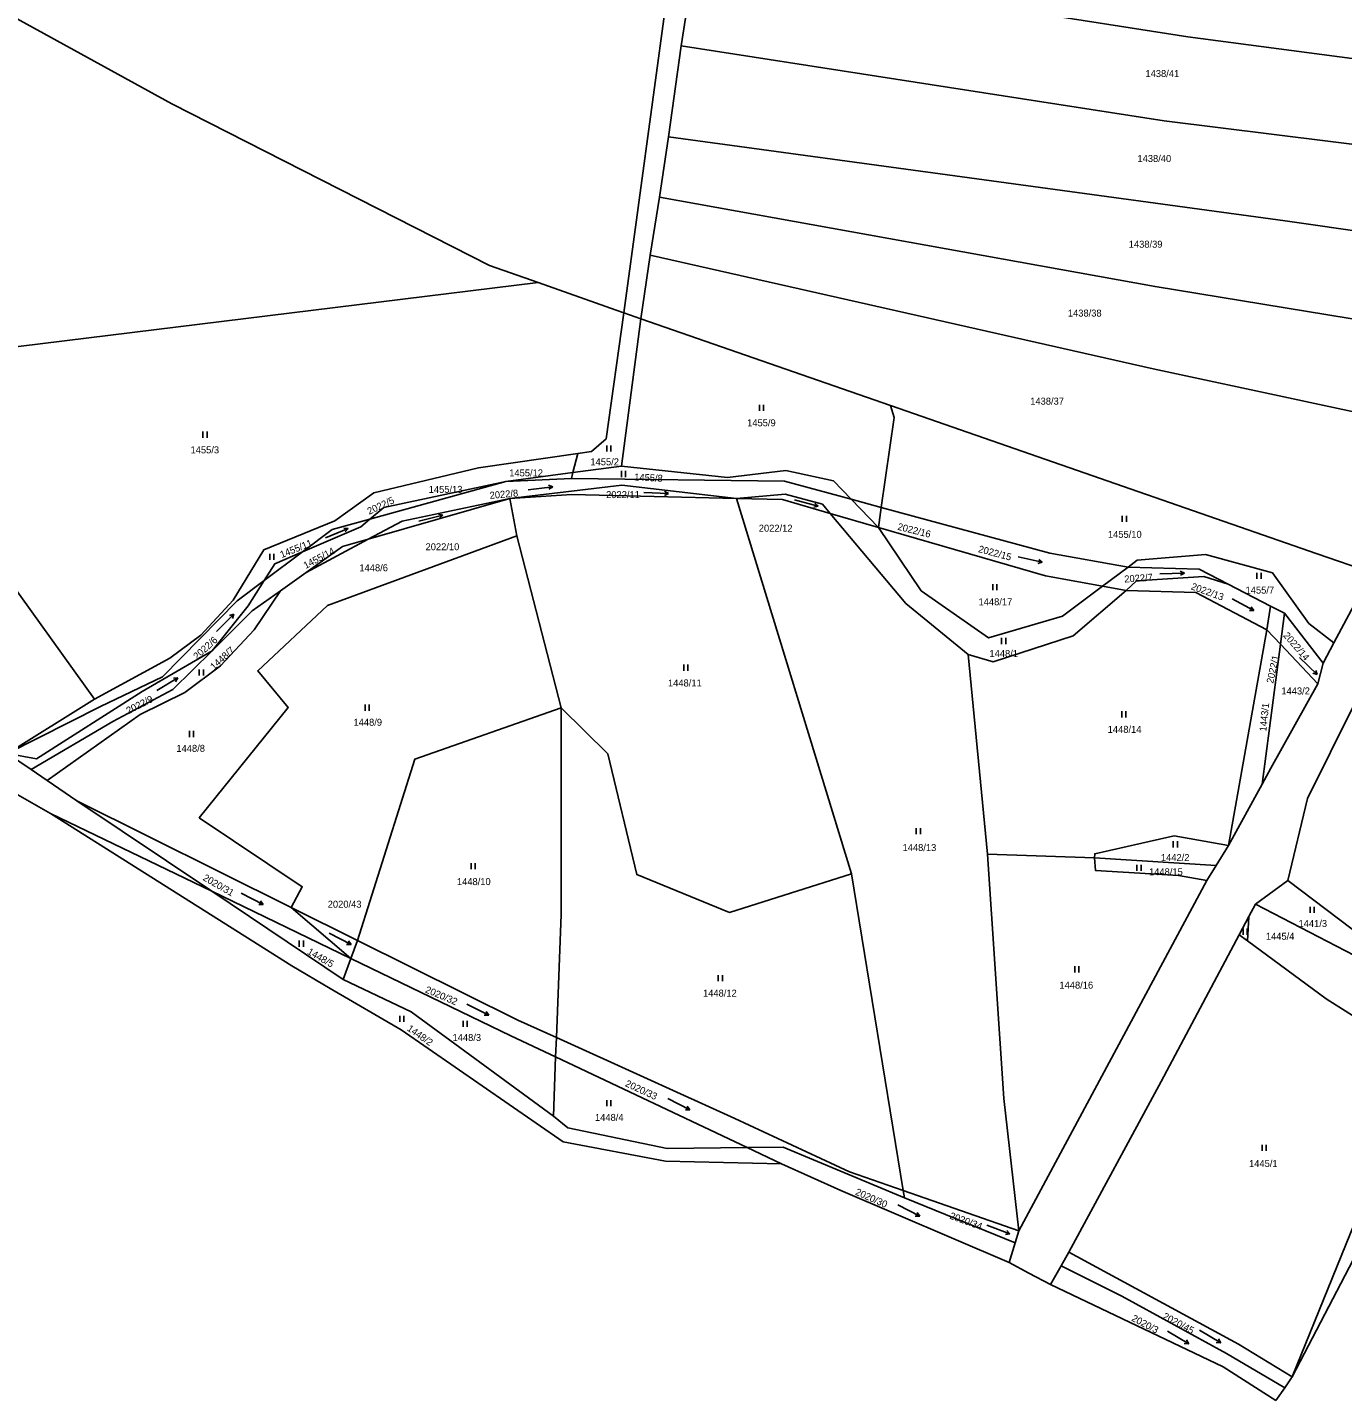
# Model space of a CAD drawing. Extents: x -793666 to -785424, y -1118958 to -1108761.
# Drawn here: x -787563.2 to -787242.9, y -1118639.5 to -1118305 of the extents above; entities that cross this region are included whole.
import ezdxf

# ---------------------------------------------------------------- set-up
doc = ezdxf.new("R2010")
doc.units = 0
for name, color, linetype in [('Hranice parcel', 7, 'Continuous'), ('Parcelní čísla', 7, 'Continuous'), ('Značky kultur', 7, 'Continuous')]:
    doc.layers.add(name, color=color, linetype=linetype)

msp = doc.modelspace()

# ---------------------------------------------------------------- linework, layer by layer
at = {"layer": 'Hranice parcel'}
for p, q in [((-787417.9, -1118374.55), (-787402.57, -1118261.44)), ((-787404, -1118309.48), (-787400.74, -1118288.44)), ((-787407.09, -1118331.67), (-787404, -1118309.48)), ((-787409.24, -1118346.36), (-787407.09, -1118331.67)), ((-787411.56, -1118360.49), (-787409.24, -1118346.36)), ((-787413.8, -1118375.97), (-787411.56, -1118360.49)), ((-787629.87, -1118390.63), (-787438.82, -1118367.18)), ((-787418.52, -1118411.86), (-787413.8, -1118375.97)), ((-787413.8, -1118375.97), (-787417.9, -1118374.55)), ((-787413.8, -1118375.97), (-787353.01, -1118397.09)), ((-787429.1, -1118408.81), (-787430.33, -1118413.45)), ((-787446.64, -1118415.65), (-787430.33, -1118413.45)), ((-787430.33, -1118413.45), (-787430.71, -1118414.9)), ((-787430.33, -1118413.45), (-787418.52, -1118411.86)), ((-787479.78, -1118424.76), (-787446.64, -1118415.65)), ((-787446.64, -1118415.65), (-787430.71, -1118414.9)), ((-787445.72, -1118419.74), (-787480.16, -1118429.65)), ((-787443.96, -1118428.82), (-787445.72, -1118419.74)), ((-787362.53, -1118511.14), (-787390.51, -1118419.78)), ((-787362.57, -1118419.94), (-787355.26, -1118421.92)), ((-787355.96, -1118426.79), (-787362.57, -1118419.94)), ((-787355.96, -1118426.79), (-787367.67, -1118423.39)), ((-787355.26, -1118421.92), (-787355.96, -1118426.79)), ((-787495.27, -1118437.74), (-787480.16, -1118429.65)), ((-787433.19, -1118470.77), (-787443.96, -1118428.82)), ((-787505.48, -1118439.7), (-787496.22, -1118432.75)), ((-787495.27, -1118437.74), (-787501.57, -1118442.22)), ((-787295.11, -1118436.5), (-787301.35, -1118441.14)), ((-787235.84, -1118437.8), (-787245.01, -1118454.92)), ((-787295.65, -1118442.18), (-787301.35, -1118441.14)), ((-787270.8, -1118440.61), (-787260.47, -1118445.96)), ((-787260.47, -1118445.96), (-787261.35, -1118451.77)), ((-787257.07, -1118447.72), (-787260.47, -1118445.96)), ((-787258.06, -1118455.25), (-787257.07, -1118447.72)), ((-787257.07, -1118447.72), (-787247.66, -1118459.87)), ((-787261.35, -1118451.77), (-787270.69, -1118504.24)), ((-787258.06, -1118455.25), (-787261.35, -1118451.77)), ((-787329.35, -1118506.42), (-787334.09, -1118457.75)), ((-787262.52, -1118489.37), (-787258.06, -1118455.25)), ((-787248.91, -1118464.91), (-787258.06, -1118455.25)), ((-787245.01, -1118454.92), (-787247.66, -1118459.87)), ((-787247.66, -1118459.87), (-787248.91, -1118464.91)), ((-787546.81, -1118468.61), (-787568, -1118481.84)), ((-787562.27, -1118485.78), (-787568, -1118481.84)), ((-787557.53, -1118496.48), (-787576.6, -1118485.68)), ((-787558.39, -1118488.44), (-787562.27, -1118485.78)), ((-787551.16, -1118493.41), (-787558.39, -1118488.44)), ((-787270.69, -1118504.24), (-787262.52, -1118489.37)), ((-787518.29, -1118515.43), (-787551.16, -1118493.41)), ((-787498.93, -1118519.35), (-787551.16, -1118493.41)), ((-787498.76, -1118533.58), (-787557.53, -1118496.48)), ((-787518.29, -1118515.43), (-787557.53, -1118496.48)), ((-787270.69, -1118504.24), (-787273.7, -1118509.14)), ((-787329.35, -1118506.42), (-787303.31, -1118507.31)), ((-787303.31, -1118507.31), (-787273.7, -1118509.14)), ((-787349.9, -1118588.32), (-787362.53, -1118511.14)), ((-787273.7, -1118509.14), (-787275.95, -1118512.79)), ((-787275.95, -1118512.79), (-787321.76, -1118598.1)), ((-787264.16, -1118518.6), (-787256.27, -1118512.79)), ((-787518.29, -1118515.43), (-787484.4, -1118531.8)), ((-787486.26, -1118536.89), (-787518.29, -1118515.43)), ((-787484.4, -1118531.8), (-787498.93, -1118519.35)), ((-787482.79, -1118527.37), (-787498.93, -1118519.35)), ((-787265.75, -1118521.6), (-787264.16, -1118518.6)), ((-787268.09, -1118526), (-787265.75, -1118521.6)), ((-787265.75, -1118521.6), (-787266.06, -1118527.5)), ((-787482.79, -1118527.37), (-787484.4, -1118531.8)), ((-787266.06, -1118527.5), (-787268.09, -1118526)), ((-787489.41, -1118539.07), (-787498.76, -1118533.58)), ((-787484.4, -1118531.8), (-787486.26, -1118536.89)), ((-787472.16, -1118549.19), (-787489.41, -1118539.07)), ((-787434.54, -1118555.77), (-787434.36, -1118551.03)), ((-787435.08, -1118570.18), (-787434.54, -1118555.77)), ((-787434.54, -1118555.77), (-787387.94, -1118577.81)), ((-787217.11, -1118560.49), (-787255.19, -1118633.7)), ((-787379.56, -1118581.78), (-787387.94, -1118577.81)), ((-787365.06, -1118588.3), (-787379.56, -1118581.78)), ((-787324.12, -1118605.87), (-787365.06, -1118588.3)), ((-787349.61, -1118590.09), (-787349.9, -1118588.32)), ((-787321.76, -1118598.1), (-787349.9, -1118588.32)), ((-787322.66, -1118601.06), (-787349.61, -1118590.09)), ((-787321.76, -1118598.1), (-787322.66, -1118601.06)), ((-787322.66, -1118601.06), (-787324.12, -1118605.87)), ((-787311.47, -1118606.64), (-787309.57, -1118603.31)), ((-787311.47, -1118606.64), (-787314.06, -1118611.19)), ((-787272.02, -1118631.21), (-787314.06, -1118611.19)), ((-787259.14, -1118639.46), (-787272.02, -1118631.21)), ((-787255.19, -1118633.7), (-787257, -1118636.34)), ((-787259.14, -1118639.46), (-787257, -1118636.34))]:
    msp.add_line(p, q, dxfattribs=at)
for points in [[(-787438.82, -1118367.18), (-787450.68, -1118362.99), (-787528.04, -1118323.66), (-787620.89, -1118272.58)], [(-787170.53, -1118319.75), (-787225.85, -1118314.51), (-787280.62, -1118307.34), (-787400.74, -1118288.44)], [(-787181.11, -1118339.31), (-787219.07, -1118336.16), (-787286.38, -1118327.77), (-787404, -1118309.48)], [(-787192.93, -1118361.27), (-787256.87, -1118352.13), (-787407.09, -1118331.67)], [(-787204.45, -1118381.96), (-787288.56, -1118368.12), (-787409.24, -1118346.36)], [(-787216.75, -1118403.66), (-787289.04, -1118388.21), (-787411.56, -1118360.49)], [(-787417.9, -1118374.55), (-787419.84, -1118373.88), (-787438.82, -1118367.18)], [(-787417.9, -1118374.55), (-787422.24, -1118405.26), (-787425.81, -1118408.34), (-787429.1, -1118408.81)], [(-787617.06, -1118409.72), (-787598.89, -1118396.21), (-787546.81, -1118468.61)], [(-787355.26, -1118421.92), (-787352.13, -1118400.04), (-787353.01, -1118397.09)], [(-787353.01, -1118397.09), (-787249.07, -1118433.2), (-787235.84, -1118437.8)], [(-787546.81, -1118468.61), (-787528.49, -1118458.66), (-787520.97, -1118453.07), (-787513.06, -1118444.49), (-787505.63, -1118432.22), (-787488.3, -1118425.19), (-787478.83, -1118418.38), (-787453.3, -1118412.3), (-787429.1, -1118408.81)], [(-787362.57, -1118419.94), (-787366.89, -1118415.46), (-787378.48, -1118412.97), (-787392.73, -1118414.6), (-787418.52, -1118411.86)], [(-787479.78, -1118424.76), (-787476.41, -1118421.91), (-787446.64, -1118415.65)], [(-787445.72, -1118419.74), (-787418.4, -1118416.52), (-787390.51, -1118419.78)], [(-787430.71, -1118414.9), (-787378.79, -1118415.54), (-787362.57, -1118419.94)], [(-787480.16, -1118429.65), (-787471.92, -1118425.24), (-787445.72, -1118419.74)], [(-787390.51, -1118419.78), (-787430.63, -1118418.78), (-787445.72, -1118419.74)], [(-787390.51, -1118419.78), (-787378.63, -1118418.69), (-787369.58, -1118421.11), (-787367.67, -1118423.39)], [(-787367.67, -1118423.39), (-787379.27, -1118420.02), (-787390.51, -1118419.78)], [(-787367.67, -1118423.39), (-787349.3, -1118445.29), (-787334.09, -1118457.75)], [(-787355.26, -1118421.92), (-787314.2, -1118433.05), (-787295.11, -1118436.5)], [(-787496.22, -1118432.75), (-787482, -1118426.63), (-787479.78, -1118424.76)], [(-787496.22, -1118432.75), (-787488.92, -1118427.27), (-787479.78, -1118424.76)], [(-787301.35, -1118441.14), (-787315.26, -1118438.6), (-787355.96, -1118426.79)], [(-787301.35, -1118441.14), (-787311.09, -1118448.38), (-787329.12, -1118453.71), (-787345.51, -1118442.25), (-787355.96, -1118426.79)], [(-787498.93, -1118519.35), (-787496.26, -1118514.3), (-787521.34, -1118497.53), (-787499.69, -1118470.65), (-787507.08, -1118461.72), (-787490.08, -1118445.83), (-787443.96, -1118428.82)], [(-787480.16, -1118429.65), (-787486.45, -1118431.46), (-787495.27, -1118437.74)], [(-787505.48, -1118439.7), (-787502.91, -1118435.63), (-787496.22, -1118432.75)], [(-787245.01, -1118454.92), (-787251.12, -1118450.22), (-787260.01, -1118437.85), (-787276.27, -1118433.38), (-787292.97, -1118434.78), (-787295.11, -1118436.5)], [(-787295.11, -1118436.5), (-787277.84, -1118436.97), (-787270.8, -1118440.61)], [(-787568, -1118481.84), (-787545.35, -1118470.42), (-787530.31, -1118463.17), (-787512.07, -1118444.65), (-787505.48, -1118439.7)], [(-787518.2, -1118456.82), (-787509.39, -1118445.9), (-787505.48, -1118439.7)], [(-787295.65, -1118442.18), (-787293.11, -1118439.81), (-787276.71, -1118438.78), (-787270.8, -1118440.61)], [(-787558.39, -1118488.44), (-787535.74, -1118472.39), (-787524.84, -1118466.98), (-787516.12, -1118460.49), (-787507.98, -1118451.76), (-787501.57, -1118442.22)], [(-787501.57, -1118442.22), (-787508.48, -1118447.13), (-787518.2, -1118456.82)], [(-787334.09, -1118457.75), (-787328.03, -1118459.56), (-787308.54, -1118453.2), (-787295.65, -1118442.18)], [(-787261.35, -1118451.77), (-787278.62, -1118442.65), (-787295.65, -1118442.18)], [(-787568, -1118481.84), (-787560.99, -1118483.15), (-787535.23, -1118466.77), (-787518.2, -1118456.82)], [(-787518.2, -1118456.82), (-787527.72, -1118466.31), (-787542.34, -1118474.1), (-787562.27, -1118485.78)], [(-787248.91, -1118464.91), (-787260.38, -1118485.47), (-787262.52, -1118489.37)], [(-787482.79, -1118527.37), (-787468.81, -1118483.23), (-787433.19, -1118470.77)], [(-787434.36, -1118551.03), (-787433.23, -1118521.06), (-787433.19, -1118470.77)], [(-787433.19, -1118470.77), (-787421.86, -1118481.96), (-787414.81, -1118511.34), (-787392.19, -1118520.57), (-787362.53, -1118511.14)], [(-787256.27, -1118512.79), (-787251.49, -1118492.81), (-787240.28, -1118470.25)], [(-787270.69, -1118504.24), (-787283.94, -1118501.92), (-787303.28, -1118506.29), (-787303.31, -1118507.31)], [(-787321.76, -1118598.1), (-787325.42, -1118565.9), (-787329.35, -1118506.42)], [(-787303.31, -1118507.31), (-787303.09, -1118510.36), (-787282.85, -1118511.55), (-787275.95, -1118512.79)], [(-787264.16, -1118518.6), (-787240, -1118531.03), (-787237.55, -1118526.92), (-787256.27, -1118512.79)], [(-787434.36, -1118551.03), (-787443.72, -1118546.78), (-787482.79, -1118527.37)], [(-787268.09, -1118526), (-787287.1, -1118561.77), (-787309.57, -1118603.31)], [(-787217.11, -1118560.49), (-787246.95, -1118541.62), (-787266.06, -1118527.5)], [(-787484.4, -1118531.8), (-787445.44, -1118550.61), (-787434.54, -1118555.77)], [(-787435.08, -1118570.18), (-787469.71, -1118544.75), (-787486.26, -1118536.89)], [(-787379.56, -1118581.78), (-787407.83, -1118581.15), (-787432.67, -1118576.48), (-787472.16, -1118549.19)], [(-787349.9, -1118588.32), (-787363.02, -1118583.76), (-787390.92, -1118570.77), (-787434.36, -1118551.03)], [(-787255.19, -1118633.7), (-787235.57, -1118585.27), (-787217.11, -1118560.49)], [(-787387.94, -1118577.81), (-787407.41, -1118578.04), (-787431.54, -1118573.02), (-787435.08, -1118570.18)], [(-787349.61, -1118590.09), (-787379.13, -1118577.71), (-787387.94, -1118577.81)], [(-787309.57, -1118603.31), (-787268.28, -1118625.73), (-787255.19, -1118633.7)], [(-787314.06, -1118611.19), (-787319.31, -1118608.45), (-787324.12, -1118605.87)], [(-787257, -1118636.34), (-787271.2, -1118628.01), (-787296.71, -1118614.01), (-787311.47, -1118606.64)]]:
    msp.add_lwpolyline(points, dxfattribs=at)
at = {"layer": 'Značky kultur'}
for p, q in [((-787384.91, -1118398.41), (-787384.91, -1118396.91)), ((-787383.91, -1118398.41), (-787383.91, -1118396.91)), ((-787520.42, -1118404.95), (-787520.42, -1118403.45)), ((-787519.42, -1118404.95), (-787519.42, -1118403.45)), ((-787422.09, -1118408.31), (-787422.09, -1118406.81)), ((-787421.09, -1118408.31), (-787421.09, -1118406.81)), ((-787418.54, -1118414.52), (-787418.54, -1118413.02)), ((-787417.54, -1118414.52), (-787417.54, -1118413.02)), ((-787441.22, -1118417.62), (-787435.26, -1118416.89)), ((-787435.26, -1118416.89), (-787436.3, -1118416.51)), ((-787435.26, -1118416.89), (-787436.17, -1118417.51)), ((-787413.07, -1118418.32), (-787407.08, -1118418.53)), ((-787407.08, -1118418.53), (-787408.07, -1118419)), ((-787407.08, -1118418.53), (-787408.03, -1118418)), ((-787376.38, -1118420.1), (-787370.59, -1118421.65)), ((-787370.59, -1118421.65), (-787371.4, -1118420.91)), ((-787467.83, -1118425.26), (-787462.01, -1118423.81)), ((-787462.01, -1118423.81), (-787463.08, -1118423.56)), ((-787462.01, -1118423.81), (-787462.84, -1118424.53)), ((-787370.59, -1118421.65), (-787371.66, -1118421.88)), ((-787296.55, -1118425.45), (-787296.55, -1118423.95)), ((-787295.55, -1118425.45), (-787295.55, -1118423.95)), ((-787490.62, -1118429.31), (-787485.06, -1118427.07)), ((-787485.06, -1118427.07), (-787486.15, -1118426.97)), ((-787485.06, -1118427.07), (-787485.78, -1118427.9)), ((-787504.13, -1118434.72), (-787504.13, -1118433.22)), ((-787503.13, -1118434.72), (-787503.13, -1118433.22)), ((-787321.9, -1118433.94), (-787316.05, -1118435.29)), ((-787316.05, -1118435.29), (-787316.89, -1118434.58)), ((-787316.05, -1118435.29), (-787317.12, -1118435.56)), ((-787287.43, -1118438.12), (-787281.43, -1118437.91)), ((-787281.43, -1118437.91), (-787282.43, -1118437.45)), ((-787281.43, -1118437.91), (-787282.39, -1118438.45)), ((-787263.78, -1118439.33), (-787263.78, -1118437.83)), ((-787262.78, -1118439.33), (-787262.78, -1118437.83)), ((-787328.1, -1118442.12), (-787328.1, -1118440.62)), ((-787327.1, -1118442.12), (-787327.1, -1118440.62)), ((-787269.81, -1118444.22), (-787264.51, -1118447.03)), ((-787517.14, -1118452.16), (-787512.9, -1118447.91)), ((-787512.9, -1118447.91), (-787513.95, -1118448.25)), ((-787512.9, -1118447.91), (-787513.24, -1118448.96)), ((-787264.51, -1118447.03), (-787265.61, -1118447.02)), ((-787264.51, -1118447.03), (-787265.14, -1118446.13)), ((-787325.95, -1118455.22), (-787325.95, -1118453.72)), ((-787324.95, -1118455.22), (-787324.95, -1118453.72)), ((-787521.32, -1118462.9), (-787521.32, -1118461.4)), ((-787520.32, -1118462.9), (-787520.32, -1118461.4)), ((-787403.34, -1118461.71), (-787403.34, -1118460.21)), ((-787402.34, -1118461.71), (-787402.34, -1118460.21)), ((-787253.39, -1118458.48), (-787249.08, -1118462.65)), ((-787531.64, -1118466.53), (-787526.5, -1118463.44)), ((-787526.5, -1118463.44), (-787527.59, -1118463.52)), ((-787526.5, -1118463.44), (-787527.08, -1118464.38)), ((-787249.08, -1118462.65), (-787250.13, -1118462.33)), ((-787249.08, -1118462.65), (-787249.43, -1118461.61)), ((-787480.94, -1118471.46), (-787480.94, -1118469.96)), ((-787479.94, -1118471.46), (-787479.94, -1118469.96)), ((-787296.7, -1118473.09), (-787296.7, -1118471.59)), ((-787295.7, -1118473.09), (-787295.7, -1118471.59)), ((-787523.7, -1118477.86), (-787523.7, -1118476.36)), ((-787522.7, -1118477.86), (-787522.7, -1118476.36)), ((-787346.73, -1118501.53), (-787346.73, -1118500.03)), ((-787345.73, -1118501.53), (-787345.73, -1118500.03)), ((-787284.15, -1118504.75), (-787284.15, -1118503.25)), ((-787283.15, -1118504.75), (-787283.15, -1118503.25)), ((-787455.14, -1118510.06), (-787455.14, -1118508.56)), ((-787454.14, -1118510.06), (-787454.14, -1118508.56)), ((-787292.98, -1118510.47), (-787292.98, -1118508.97)), ((-787291.98, -1118510.47), (-787291.98, -1118508.97)), ((-787511.1, -1118515.92), (-787505.76, -1118518.65)), ((-787505.76, -1118518.65), (-787506.4, -1118517.76)), ((-787505.76, -1118518.65), (-787506.85, -1118518.65)), ((-787250.82, -1118520.69), (-787250.82, -1118519.19)), ((-787249.82, -1118520.69), (-787249.82, -1118519.19)), ((-787267.14, -1118526.02), (-787267.14, -1118524.52)), ((-787266.14, -1118526.02), (-787266.14, -1118524.52)), ((-787496.98, -1118528.92), (-787496.98, -1118527.42)), ((-787495.98, -1118528.92), (-787495.98, -1118527.42)), ((-787489.68, -1118525.65), (-787484.34, -1118528.38)), ((-787484.34, -1118528.38), (-787484.98, -1118527.49)), ((-787484.34, -1118528.38), (-787485.43, -1118528.38)), ((-787308.11, -1118535.2), (-787308.11, -1118533.7)), ((-787307.11, -1118535.2), (-787307.11, -1118533.7)), ((-787394.93, -1118537.32), (-787394.93, -1118535.82)), ((-787393.93, -1118537.32), (-787393.93, -1118535.82)), ((-787456.19, -1118542.88), (-787450.85, -1118545.61)), ((-787450.85, -1118545.61), (-787451.49, -1118544.72)), ((-787472.5, -1118547.26), (-787472.5, -1118545.76)), ((-787471.5, -1118547.26), (-787471.5, -1118545.76)), ((-787457.09, -1118548.46), (-787457.09, -1118546.96)), ((-787456.09, -1118548.46), (-787456.09, -1118546.96)), ((-787450.85, -1118545.61), (-787451.94, -1118545.61)), ((-787422.07, -1118567.78), (-787422.07, -1118566.28)), ((-787421.07, -1118567.78), (-787421.07, -1118566.28)), ((-787407.2, -1118565.9), (-787401.86, -1118568.63)), ((-787401.86, -1118568.63), (-787402.5, -1118567.74)), ((-787401.86, -1118568.63), (-787402.95, -1118568.63)), ((-787262.5, -1118578.64), (-787262.5, -1118577.14)), ((-787261.5, -1118578.64), (-787261.5, -1118577.14)), ((-787351.22, -1118591.82), (-787345.88, -1118594.55)), ((-787345.88, -1118594.55), (-787346.97, -1118594.55)), ((-787345.88, -1118594.55), (-787346.52, -1118593.66)), ((-787329.54, -1118596.74), (-787323.94, -1118598.89)), ((-787323.94, -1118598.89), (-787324.67, -1118598.07)), ((-787323.94, -1118598.89), (-787325.03, -1118599.01)), ((-787285.52, -1118622.53), (-787280.38, -1118625.62)), ((-787280.38, -1118625.62), (-787280.96, -1118624.69)), ((-787277.73, -1118622.31), (-787272.59, -1118625.4)), ((-787272.59, -1118625.4), (-787273.17, -1118624.47)), ((-787280.38, -1118625.62), (-787281.47, -1118625.55)), ((-787272.59, -1118625.4), (-787273.68, -1118625.33))]:
    msp.add_line(p, q, dxfattribs=at)

# ---------------------------------------------------------------- texts
at = {"layer": 'Parcelní čísla'}
for s, p in [('1438/41', (-787290.92, -1118317.11)), ('1438/40', (-787292.87, -1118337.79)), ('1438/39', (-787294.99, -1118358.67)), ('1438/38', (-787309.81, -1118375.44)), ('1438/37', (-787318.98, -1118396.9)), ('1455/9', (-787387.91, -1118402.16)), ('1455/3', (-787523.45, -1118408.76)), ('1455/2', (-787426.08, -1118411.66)), ('1455/12', (-787445.84, -1118414.37)), ('1455/13', (-787465.45, -1118418.38)), ('2022/11', (-787422.25, -1118419.66)), ('2022/12', (-787385.08, -1118427.84)), ('1455/10', (-787300.06, -1118429.33)), ('2022/10', (-787466.22, -1118432.36)), ('1448/6', (-787482.33, -1118437.48)), ('1455/7', (-787266.54, -1118442.92)), ('1448/17', (-787331.57, -1118445.76)), ('1448/1', (-787328.91, -1118458.36)), ('1448/11', (-787407.19, -1118465.54)), ('1443/2', (-787257.83, -1118467.48)), ('1448/9', (-787483.77, -1118475.11)), ('1448/14', (-787300.11, -1118476.83)), ('1448/8', (-787526.89, -1118481.46)), ('1448/13', (-787350.07, -1118505.63)), ('1442/2', (-787287.16, -1118508.05)), ('1448/15', (-787290.05, -1118511.53)), ('1448/10', (-787458.58, -1118513.92)), ('2020/43', (-787490.04, -1118519.42)), ('1441/3', (-787253.65, -1118524.13)), ('1445/4', (-787261.6, -1118527.23)), ('1448/16', (-787311.87, -1118539.13)), ('1448/12', (-787398.66, -1118541.09)), ('1448/3', (-787459.65, -1118551.89)), ('1448/4', (-787424.96, -1118571.35)), ('1445/1', (-787265.7, -1118582.59))]:
    msp.add_text(s, height=1.7, dxfattribs=at).set_placement(p)
for s, rotation, p in [('1455/8', 357, (-787415.45, -1118415.34)), ('2022/8', 5, (-787450.53, -1118419.85)), ('2022/5', 25, (-787479.93, -1118423.72)), ('2022/16', 346, (-787351.42, -1118427.34)), ('1455/11', 22, (-787501.25, -1118434.29)), ('2022/15', 345, (-787331.75, -1118432.78)), ('1455/14', 28, (-787495.4, -1118436.94)), ('2022/7', 4, (-787296.01, -1118440.23)), ('2022/13', 340, (-787279.96, -1118441.83)), ('2022/6', 42, (-787521.86, -1118459.11)), ('2022/14', 311, (-787257.48, -1118453.2)), ('1448/7', 42, (-787517.74, -1118461.61)), ('2022/1', 78, (-787259.82, -1118464.9)), ('2022/9', 27, (-787538.57, -1118472.3)), ('1443/1', 84, (-787261.5, -1118476.56)), ('2020/31', 330, (-787520.6, -1118512.61)), ('1448/5', 330, (-787495.18, -1118530.59)), ('2020/32', 337, (-787466.46, -1118540.01)), ('1448/2', 325, (-787470.88, -1118549.2)), ('2020/33', 335, (-787417.75, -1118562.83)), ('2020/30', 336, (-787361.73, -1118589.25)), ('2020/34', 340, (-787338.75, -1118595.12)), ('2020/45', 332, (-787286.89, -1118619.45)), ('2020/3', 332, (-787294.46, -1118619.93))]:
    msp.add_text(s, height=1.7, rotation=rotation, dxfattribs=at).set_placement(p)

doc.saveas('drawing.dxf')
